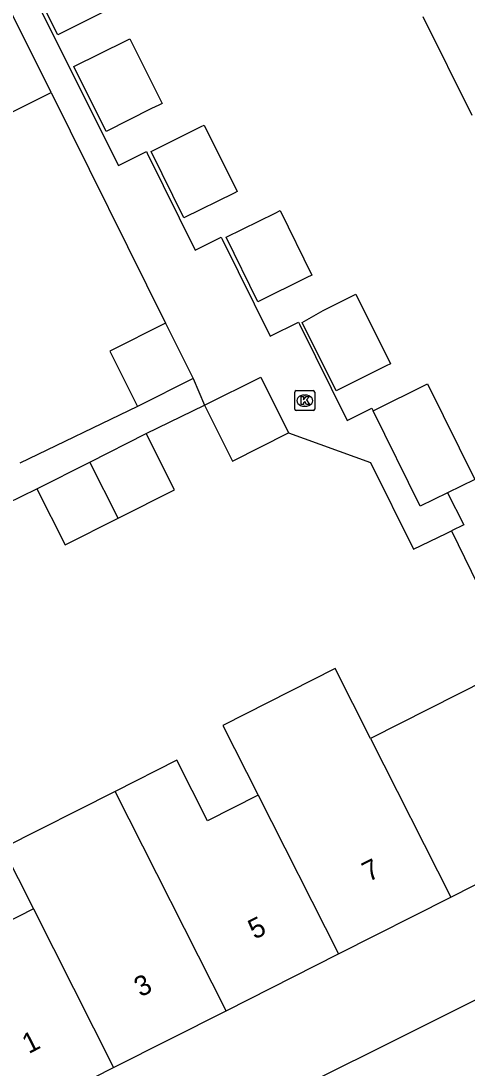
# Model space of a CAD drawing. Extents: x 157793 to 159380, y 380882 to 382313.
# Drawn here: x 158255.4 to 158277.7, y 381551.8 to 381604.2 of the extents above; entities that cross this region are included whole.
import ezdxf

# ---------------------------------------------------------------- set-up
doc = ezdxf.new("R2010")
doc.units = 0
for name, color, linetype in [('IMGEO_Kolk', 7, 'Continuous'), ('IMGEO_Pand', 7, 'Continuous'), ('IMGEO_Pand_nummerreeks', 7, 'Continuous'), ('IMGEO_Voetpad_open', 7, 'Continuous')]:
    doc.layers.add(name, color=color, linetype=linetype)

msp = doc.modelspace()

# ---------------------------------------------------------------- linework, layer by layer
at = {"layer": 'IMGEO_Kolk'}
for p, q in [((158269.09, 381584.78), (158269.09, 381585.632)), ((158269.165, 381585.706), (158270.017, 381585.706)), ((158269.578, 381585.486), (158269.603, 381585.486)), ((158270.091, 381585.632), (158270.091, 381584.78)), ((158270.017, 381584.706), (158269.165, 381584.706)), ((158269.601, 381584.926), (158269.576, 381584.926))]:
    msp.add_line(p, q, dxfattribs=at)
for points in [[(158269.09, 381584.78), (158269.09, 381585.632)], [(158269.165, 381585.706), (158270.017, 381585.706)], [(158269.411, 381585.406), (158269.534, 381585.406), (158269.534, 381585.255), (158269.664, 381585.406), (158269.828, 381585.406), (158269.682, 381585.255), (158269.835, 381585.006), (158269.683, 381585.006), (158269.598, 381585.17), (158269.534, 381585.103), (158269.534, 381585.006), (158269.411, 381585.006), (158269.411, 381585.406)], [(158270.091, 381585.632), (158270.091, 381584.78)], [(158270.017, 381584.706), (158269.165, 381584.706)]]:
    msp.add_lwpolyline(points, dxfattribs=at)
for centre, start, end in [((158269.167, 381585.63), 91.552, 178.448), ((158269.167, 381585.63), 91.552, 178.448), ((158270.015, 381585.63), 1.552, 88.448), ((158270.015, 381585.63), 1.552, 88.448), ((158269.167, 381584.782), 181.552, 268.448), ((158269.167, 381584.782), 181.552, 268.448), ((158270.015, 381584.782), 271.552, 358.448), ((158270.015, 381584.782), 271.552, 358.448)]:
    msp.add_arc(centre, 0.0765, start, end, dxfattribs=at)
for centre, major_axis, ratio, start_param, end_param in [((158269.577, 381585.206), (-0.387, 0.002), 0.722429, 4.712389, 7.853982), ((158269.602, 381585.206), (-0.39, 0.002), 0.717154, 1.570796, 4.712389)]:
    msp.add_ellipse(centre, major_axis=major_axis, ratio=ratio, start_param=start_param, end_param=end_param, dxfattribs=at)
at = {"layer": 'IMGEO_Pand'}
for points in [[(158256.91, 381600.62), (158252.968, 381608.515)], [(158258.284, 381608.021), (158258.447, 381608.102), (158260.044, 381604.902), (158259.881, 381604.821), (158259.473, 381604.62), (158257.234, 381603.513), (158255.637, 381606.713)], [(158277.965, 381599.465), (158275.522, 381604.411)], [(158260.677, 381603.227), (158260.84, 381603.308), (158262.454, 381600.075), (158262.291, 381599.994), (158261.93, 381599.813), (158259.649, 381598.675), (158258.03, 381601.918), (158260.677, 381603.227)], [(158251.122, 381597.731), (158256.91, 381600.62)], [(158264.405, 381598.913), (158264.566, 381598.993), (158266.212, 381595.66), (158266.051, 381595.58), (158263.545, 381594.343), (158261.899, 381597.674), (158264.405, 381598.913)], [(158268.106, 381594.59), (158268.356, 381594.713), (158269.948, 381591.49), (158269.698, 381591.367), (158267.243, 381590.154), (158265.651, 381593.376), (158268.106, 381594.59)], [(158271.947, 381590.428), (158272.154, 381590.53), (158273.877, 381587.042), (158273.67, 381586.94), (158271.16, 381585.698), (158269.469, 381589.121), (158270.512, 381589.719), (158271.947, 381590.428)], [(158262.626, 381589.074), (158259.842, 381587.684), (158261.224, 381584.916)], [(158262.626, 381589.074), (158264.008, 381586.306)], [(158264.008, 381586.306), (158261.224, 381584.916)], [(158264.582, 381584.978), (158267.389, 381586.38), (158268.783, 381583.589)], [(158273.006, 381584.704), (158275.736, 381586.054), (158278.1, 381581.269)], [(158264.582, 381584.978), (158265.976, 381582.187), (158268.783, 381583.589)], [(158276.724, 381580.589), (158275.369, 381579.92), (158273.006, 381584.704)], [(158258.834, 381582.135), (158261.649, 381583.558)], [(158260.254, 381579.326), (158263.069, 381580.749), (158261.649, 381583.558)], [(158256.191, 381580.799), (158258.834, 381582.135)], [(158260.254, 381579.326), (158258.834, 381582.135)], [(158278.1, 381581.269), (158276.724, 381580.589)], [(158256.191, 381580.799), (158257.611, 381577.99), (158260.254, 381579.326)], [(158272.883, 381568.307), (158271.114, 381571.806), (158265.492, 381568.964), (158267.261, 381565.465)], [(158276.895, 381560.371), (158282.724, 381563.318), (158278.712, 381571.254), (158272.883, 381568.307)], [(158272.883, 381568.307), (158276.895, 381560.371)], [(158267.261, 381565.465), (158264.72, 381564.181), (158263.185, 381567.218), (158260.103, 381565.66)], [(158260.103, 381565.66), (158254.48, 381562.818), (158256.016, 381559.78)], [(158265.651, 381554.686), (158260.103, 381565.66)], [(158267.261, 381565.465), (158271.273, 381557.529)], [(158256.016, 381559.78), (158253.036, 381558.274), (158251.726, 381560.865), (158247.175, 381558.564)], [(158271.273, 381557.529), (158276.895, 381560.371)], [(158256.016, 381559.78), (158260.027, 381551.844)], [(158265.651, 381554.686), (158271.273, 381557.529)], [(158248.865, 381555.221), (158250.569, 381556.082), (158254.201, 381548.898), (158260.027, 381551.844)], [(158260.027, 381551.844), (158265.651, 381554.686)]]:
    msp.add_lwpolyline(points, dxfattribs=at)
at = {"layer": 'IMGEO_Voetpad_open'}
for points in [[(158255.452, 381606.621), (158257.845, 381601.827), (158260.271, 381596.966), (158261.671, 381597.665), (158261.712, 381597.581), (158264.106, 381592.734), (158265.416, 381593.381), (158265.464, 381593.284), (158267.858, 381588.438), (158269.275, 381589.138), (158269.324, 381589.038), (158271.708, 381584.211), (158272.947, 381584.823), (158273.006, 381584.704)], [(158256.91, 381600.62), (158262.626, 381589.074)], [(158264.008, 381586.306), (158264.582, 381584.978)], [(158261.224, 381584.916), (158255.329, 381582.086)], [(158261.649, 381583.558), (158264.582, 381584.978)], [(158268.783, 381583.589), (158272.878, 381582.118), (158275.023, 381577.782), (158276.667, 381578.567), (158276.93, 381578.695)], [(158253.173, 381579.335), (158256.191, 381580.799)], [(158276.724, 381580.589), (158277.547, 381578.996), (158276.93, 381578.695)], [(158276.93, 381578.695), (158282.504, 381567.278), (158284.536, 381559.787), (158283.939, 381558.16)], [(158283.939, 381558.16), (158281.897, 381557.095), (158255.625, 381543.988), (158254.456, 381543.47)]]:
    msp.add_lwpolyline(points, dxfattribs=at)

# ---------------------------------------------------------------- texts
at = {"layer": 'IMGEO_Pand_nummerreeks'}
for s, p in [('7', (158272.785, 381561.117)), ('5', (158267.08, 381558.233)), ('3', (158261.375, 381555.349)), ('1', (158255.773, 381552.516))]:
    msp.add_text(s, height=1, rotation=26.8192, dxfattribs=at).set_placement(p)

doc.saveas('drawing.dxf')
